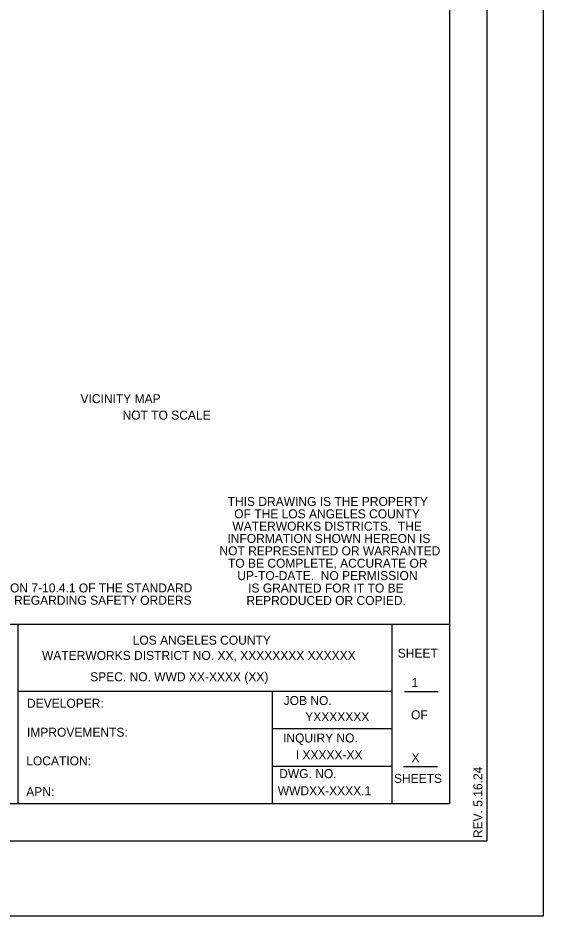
# Model space of a CAD drawing. Extents: x 837 to 1117, y 1316 to 1424.
# Drawn here: x 870.76 to 877.77, y 1398.24 to 1410.24 of the extents above; entities that cross this region are included whole.
import ezdxf

# ---------------------------------------------------------------- set-up
doc = ezdxf.new("R2010")
doc.units = 0
for name, color, linetype in [('0 (Construction)', 7, 'Continuous'), ('BASEMAP', 7, 'Continuous'), ('CONSNOTE', 7, 'Continuous'), ('LLINES', 7, 'Continuous'), ('TEXT', 7, 'Continuous')]:
    doc.layers.add(name, color=color, linetype=linetype)

msp = doc.modelspace()

# ---------------------------------------------------------------- linework, layer by layer
at = {"layer": '0 (Construction)'}
msp.add_lwpolyline([(841.77, 1422.24), (877.77, 1422.24), (877.77, 1398.24), (841.77, 1398.24)], close=True, dxfattribs=at)
at = {"layer": 'BASEMAP'}
for p, q in [((877.02, 1421.24), (877.02, 1399.24)), ((876.52, 1420.74), (876.52, 1399.74)), ((875.752, 1401.24), (870.755, 1401.24)), ((875.752, 1400.74), (874.152, 1400.74)), ((875.752, 1400.24), (874.152, 1400.24)), ((876.52, 1399.74), (843.52, 1399.74)), ((877.02, 1399.24), (843.02, 1399.24))]:
    msp.add_line(p, q, dxfattribs=at)
for points in [[(867.255, 1402.14), (876.52, 1402.14)], [(870.755, 1402.14), (870.755, 1399.74)], [(875.752, 1402.14), (875.752, 1399.74)], [(874.152, 1401.24), (874.152, 1399.74)]]:
    msp.add_lwpolyline(points, dxfattribs=at)
at = {"layer": 'LLINES'}
for p, q in [((875.919, 1401.242), (876.369, 1401.242)), ((875.907, 1400.238), (876.358, 1400.238))]:
    msp.add_line(p, q, dxfattribs=at)

# ---------------------------------------------------------------- texts
at = {"layer": 'CONSNOTE'}
msp.add_text('VICINITY MAP', height=0.12, dxfattribs=at).set_placement((871.591, 1405.093))
at = {"layer": 'LLINES'}
for s, p in [('REFER TO SECTION 7-10.4.1 OF THE STANDARD ', (869.321, 1402.564)), ('SPECIFICATIONS REGARDING SAFETY ORDERS', (869.321, 1402.399)), ('LOS ANGELES COUNTY', (872.288, 1401.866)), ('WATERWORKS DISTRICT NO. XX, XXXXXXXX XXXXXX', (871.076, 1401.662)), ('SHEET', (875.829, 1401.692)), ('SPEC. NO. WWD XX-XXXX (XX)', (871.72, 1401.377)), ('1', (876.013, 1401.299)), ('DEVELOPER: ', (870.876, 1401.023)), ('JOB NO.', (874.305, 1401.06)), ('OF', (876.007, 1400.87)), ('IMPROVEMENTS:', (870.876, 1400.636)), ('INQUIRY NO.', (874.297, 1400.559)), ('X', (876.013, 1400.295)), ('LOCATION: ', (870.866, 1400.253)), ('DWG. NO.', (874.245, 1400.083)), ('SHEETS', (875.778, 1400.019)), ('APN:', (870.866, 1399.842))]:
    msp.add_text(s, height=0.12, dxfattribs=at).set_placement(p)
msp.add_text('REV. 5.16.24', height=0.12, rotation=90, dxfattribs=at).set_placement((876.96, 1399.281))
at = {"layer": 'TEXT'}
for s, p in [('NOT TO SCALE', (872.152, 1404.873)), ('THIS DRAWING IS THE PROPERTY', (873.557, 1403.719)), ('OF THE LOS ANGELES COUNTY', (873.645, 1403.554)), ('WATERWORKS DISTRICTS.  THE', (873.62, 1403.389)), ('INFORMATION SHOWN HEREON IS', (873.554, 1403.225)), ('NOT REPRESENTED OR WARRANTED', (873.447, 1403.06)), ('TO BE COMPLETE, ACCURATE OR', (873.561, 1402.894)), ('UP-TO-DATE.  NO PERMISSION', (873.686, 1402.729)), ('IS GRANTED FOR IT TO BE', (873.83, 1402.563)), ('REPRODUCED OR COPIED.', (873.807, 1402.397)), ('YXXXXXXX', (874.593, 1400.844)), ('I XXXXX-XX', (874.466, 1400.333)), ('WWDXX-XXXX.1', (874.226, 1399.854))]:
    msp.add_text(s, height=0.12, dxfattribs=at).set_placement(p)

doc.saveas('drawing.dxf')
